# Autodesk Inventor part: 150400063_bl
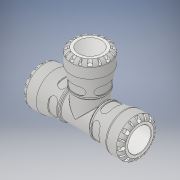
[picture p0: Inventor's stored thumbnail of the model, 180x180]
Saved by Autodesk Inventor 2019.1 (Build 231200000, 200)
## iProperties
Created: 2016-12
Part Number: 150400063_bl
Material: Generic
Description: PLASSON G-PLASS TEE 63X63X63
Document SubType Name: Modeling
Designer: KIM
Mass: 664.223 g
Surface Area: 733.008 cm^2
Volume: 474.445 cm^3
Density: 1 g/cm^3
Appearance: Default
Author: KIM
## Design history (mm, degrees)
derived "150400.ipt"
feature "Solid1::150400.ipt" dims "ScaleForDerivedMember" = 10
tag "TaggingFeature1"
body "Solid1"
other parameters: "d_" = 63 [user parameter], "E_" = 103 [user parameter], "l_" = 95 [user parameter], "A_" = 152 [user parameter], "H_" = 271 [user parameter], "d9" = 12.125 [user parameter], "d11" = 103 [user parameter], "d12" = 78.75 [user parameter], "d230" = 103 [user parameter], "d231" = 78.75 [user parameter], "d232" = 12.125 [user parameter], "d1" = 39.9 [user parameter], "d2" = 63 [user parameter], "d3" = 78.75 [user parameter], "d4" = 103 [user parameter], "d8" = 87.55 [user parameter], "d13" = 9.7 [user parameter], "d14" = 9.7 [user parameter], "d15" = 0 [user parameter], "d17" = 360 deg [user parameter], "d19" = 8 deg [user parameter], "d20" = 1.26 [user parameter], "d21" = 1.26 [user parameter], "d22" = 8 deg [user parameter], "d24" = 0 [user parameter], "d26" = 360 deg [user parameter], "d33" = 10.3 [user parameter], "d43" = 80.34 [user parameter], "d51" = 1.03 [user parameter], "d54" = 22.05 [user parameter], "d55" = 13.86 [user parameter], "d57" = 19.012 [user parameter], "d58" = 0 [user parameter], "d74" = 0 [user parameter], "d77" = 5.25 [user parameter], "d78" = 95 [user parameter], "d79" = 80.34 [user parameter], "d80" = 271 [user parameter], "d82" = 1.26 [user parameter], "d115" = 360 deg [user parameter], "d139" = 9.7 [user parameter], "d140" = 0 [user parameter], "d142" = 360 deg [user parameter], "d207" = 90 deg [user parameter], "d209" = 39.9 [user parameter], "d210" = 63 [user parameter], "d211" = 78.75 [user parameter], "d212" = 103 [user parameter], "d213" = 87.55 [user parameter], "d215" = 80.34 [user parameter], "d216" = 5.25 [user parameter], "d217" = 95 [user parameter], "d225" = 152 [user parameter], "d226" = 95 [user parameter], "d228" = 18.7425 [user parameter], "d229" = 9.7 [user parameter], "d233" = 9.7 [user parameter], "d234" = 0 [user parameter], "d236" = 360 deg [user parameter], "d238" = 8 deg [user parameter], "d239" = 8 deg [user parameter], "d240" = 1.26 [user parameter], "d241" = 1.26 [user parameter], "d243" = 0 [user parameter], "d245" = 360 deg [user parameter], "d247" = 2.06 [user parameter], "d248" = 5.7 [user parameter], "d249" = 5.7 [user parameter], "d250" = 18.7425 [user parameter], "d252" = 22.05 [user parameter], "d253" = 14.49 [user parameter], "d254" = 19.012 [user parameter], "d255" = 0 [user parameter], "d257" = 360 deg [user parameter], "d259" = 1.26 [user parameter], "d261" = 0 [user parameter], "d262" = 2.06 [user parameter], "d264" = 0 [user parameter], "d266" = 0 [user parameter], "d267" = 1.03 [user parameter]
